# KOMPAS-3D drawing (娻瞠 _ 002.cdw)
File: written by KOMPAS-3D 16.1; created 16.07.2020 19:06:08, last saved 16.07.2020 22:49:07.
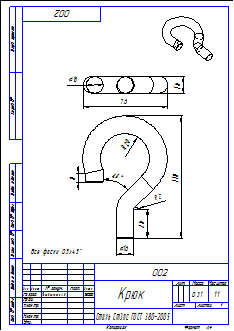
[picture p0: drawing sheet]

Sheet 1: A4, portrait

Title block, sheet 1: name: Крюк; designation: 002; material: Сталь Ст3пс ГОСТ 380-2005; mass: 0,31; scale: 1:1; sheets: 1; sheet format: A4; stored path: D:\Новая папка\работа\Чертежи\Крюк\Крюк _ 002.cdw; drawn by: Чередниченко А.В.; drawn by, date: 16.07.2020

Views: Вид 1, Сверху, Вид 2, Спереди, Вид 3, Вид:1
Referenced files in D:\Новая папка\работа\Чертежи\Крюк\: Крюк.m3d
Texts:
  user
  Все фаски 0.5х45
Dimensions and other numbers on the sheet: 002; 16; 110; 8; 26; 20; 76; 2; 1:1; 1; 0,31; 16.07.2020; 002-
